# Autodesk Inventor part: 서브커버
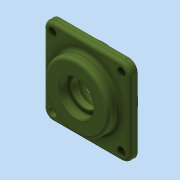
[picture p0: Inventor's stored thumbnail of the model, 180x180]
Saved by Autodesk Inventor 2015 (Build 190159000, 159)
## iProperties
Created: 2018-09
Part Number: 서브커버
Material: 알루미늄 6061
Document SubType Name: Modeling
Designer: mduedu
Density: 2.71 g/cm^3
Appearance: 올리브 녹색
Mass: 206.511 g
Surface Area: 197.007 cm^2
Volume: 76.2032 cm^3
Author: mduedu
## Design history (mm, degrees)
sketch "스케치1"
  geometry: L1 (-40, -40)-(40, -40); L2 (40, -40)-(40, 40); L3 (40, 40)-(-40, 40); L4 (-40, 40)-(-40, -40); L5 (-40, -40)-(40, 40); L6 (40, -40)-(-40, 40); 1 further point
  constraints: 12 end point, 2 midpoint, 2 parallel, 1 horizontal, 1 perpendicular
  dimensions: "d0" = 80 distance of L3.end L2.end; "d1" = 80 distance of L2.end L1.end
extrude "돌출1" new body sketch "스케치1" distance "d2" = 7; taper "d3" = 0 deg
sketch "스케치2"
  geometry: C1 r 30 at (0, 0); 1 further point
  constraints: 1 centre point, 1 coincident
  dimensions: "d4" = 60 diameter of C1
extrude "돌출2" join sketch "스케치2" distance "d5" = 10; taper "d6" = 0 deg
sketch "스케치3"
  geometry: C1 r 32.5 at (0, 0); 1 further point
  constraints: 1 centre point, 1 coincident
  dimensions: "d7" = 65 diameter of C1
extrude "돌출3" join sketch "스케치3" distance "d8" = 9; taper "d9" = 0 deg
sketch "스케치4"
  geometry: L1 (-32.5, -9)-(32.5, -9) reference; L2 (30, 17)-(-30, 17) reference; L3 (0, 17)-(0, -9); L4 (0, -9)-(20, -9); L5 (20, -9)-(20, 3); L6 (20, 3)-(0, 3); L7 (0, 3)-(0, -9); L8 (0, 3)-(12.5, 3); L9 (12.5, 3)-(12.5, 8.7); L10 (12.5, 8.7)-(0, 8.7); L11 (0, 8.7)-(0, 3); L12 (0, 8.7)-(16, 8.7); L13 (16, 8.7)-(16, 17); L14 (16, 17)-(0, 17); L15 (0, 17)-(0, 8.7); 1 further point
  constraints: 26 end point, 6 parallel, 3 horizontal, 3 perpendicular, 2 midpoint, 1 point on line
  dimensions: "d10" = 12 distance of L4.end L5.end; "d12" = 8.3 distance of L12.end L13.end; "d13" = 32 diameter of L13 L3; "d14" = 25 diameter of L9 L3; "d15" = 40 diameter of L5 L3
revolve "회전1" sketch "스케치4" stored, may be unused: angle "d16" = 90 deg
fillet "모깎기1" dims "d17" = 8
fillet "모깎기2" dims "d18" = 3
fillet "모깎기3" dims "d19" = 3
chamfer "모따기1" distance "d20" = 0.8; stored, may be unused: second distance "d21" = 2, angle "d22" = 30 deg
chamfer "모따기2" distance "d23" = 1; stored, may be unused: second distance "d24" = 2, angle "d25" = 30 deg
fillet "모깎기4" dims "d26" = 0.3
sketch "스케치5"
  geometry: A1 r 8 centre (-32, 32) between (-32, 40) and (-40, 32) reference; A2 r 8 centre (-32, -32) between (-40, -32) and (-32, -40) reference; A3 r 8 centre (32, -32) between (32, -40) and (40, -32) reference; A4 r 8 centre (32, 32) between (40, 32) and (32, 40) reference; 5 further points
  constraints: 4 coincident
hole "구멍1" sketch "스케치5" at (-32, 32), (32, 32), (32, -32), (-32, -32) diameter "d27" = 4.5; stored, may be unused: countersink angle "d31" = 90 deg, drill point angle "d33" = 118 deg; dims "d28" = 6, "d29" = 8, "d30" = 4.4, "d32" = 8
node "솔리드1"
